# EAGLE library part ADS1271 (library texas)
24-Bit Wide Bandwidth Analaog-to-Digial Converter Source: http://focus.ti.com/lit/ds/symlink/ads1271.pdf
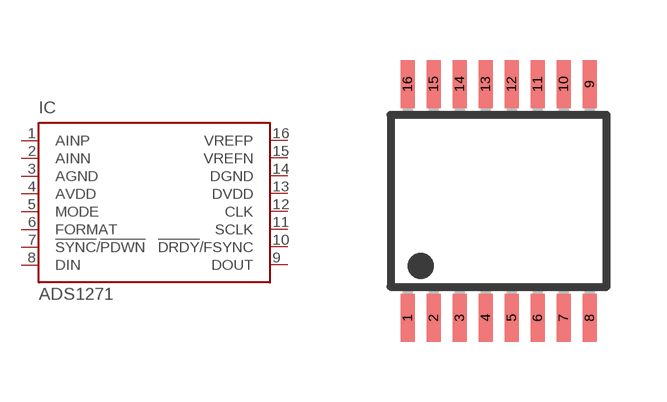
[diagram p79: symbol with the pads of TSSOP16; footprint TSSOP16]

Designator prefix IC

## ADS1271 (MF: TEXAS INSTRUMENT CONNECTORS; MPN: ADS1271IPWR; OC_FARNELL: 9968865; OC_NEWARK: 73J8186)  [TSSOP16]
1  AINP  in
2  AINN  in
3  AGND  pwr
4  AVDD  pwr
5  MODE  in
6  FORMAT  in
7  !SYNC!/!PDWN  in
8  DIN  in
9  DOUT  out
10  !DRDY!/FSYNC
11  SCLK  in
12  CLK  in
13  DVDD  in
14  DGND  in
15  VREFN  in
16  VREFP  in

## Footprint TSSOP16 (pad centres in mm)
PW (R-PDSO-G8) Source: http://focus.ti.com/lit/ds/symlink/ads1271.pdf
smd 0.35 x 1.2: 1 -2.275,-2.925; 2 -1.625,-2.925; 3 -0.975,-2.925; 4 -0.325,-2.925; 5 0.325,-2.925; 6 0.975,-2.925; 7 1.625,-2.925; 8 2.275,-2.925; 9 2.275,2.925; 10 1.625,2.925; 11 0.975,2.925; 12 0.325,2.925; 13 -0.325,2.925; 14 -0.975,2.925; 15 -1.625,2.925; 16 -2.275,2.925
